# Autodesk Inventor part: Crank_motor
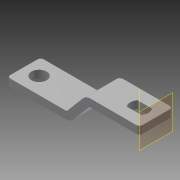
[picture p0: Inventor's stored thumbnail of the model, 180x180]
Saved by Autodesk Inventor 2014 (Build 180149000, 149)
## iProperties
Created: 2006-03
Part Number: Crank_motor
Document SubType Name: Modeling
Designer: debonom
Material: Stainless Steel, 440C
Mass: 73.5464 g
Surface Area: 52.6545 cm^2
Volume: 9.48986 cm^3
Density: 7.75 g/cm^3
Appearance: Steel
Author: debonom
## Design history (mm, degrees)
sketch "Sketch1"
  geometry: L1 (0, 0)-(-34.15, 0); L2 (0, 0)-(12.586, -15); L3 (12.586, -15)-(53.05, -15)
  constraints: 6 end point, 1 horizontal, 1 parallel
  dimensions: "d0" = 130 deg angle of L2 L1; "d1" = 87.2 horizontal distance of L3.end L1.end; "d2" = 34.15 distance of L1.start L1.end; "d3" = 15 distance between parallel lines of L3 L1
workplane "Work Plane1"
sketch "Sketch2"
  geometry: L1 (-11, 2.5)-(11, 2.5); L2 (11, 2.5)-(11, -2.5); L3 (11, -2.5)-(-11, -2.5); L4 (-11, -2.5)-(-11, 2.5); L5 (-11, 2.5)-(11, -2.5); 2 further points
  constraints: 10 end point, 2 parallel, 1 coincident, 1 horizontal, 1 midpoint, 1 perpendicular
  dimensions: "d4" = 22 distance of L1.start L1.end; "d5" = 5 distance of L3.end L1.start
sweep "Sweep1" sketch "Sketch2" dims "d6" = 0
fillet "Fillet1" dims "d7" = 7
fillet "Fillet2" dims "d8" = 2
sketch "Sketch4"
  geometry: L1 (-104.64, 11)-(17.44, 11) reference; L2 (0, 26.4)-(0, -4.4) reference; L3 (-15.823, 7.425)-(-6.178, 7.425); L4 (-6.178, 7.425)-(-6.178, 14.575); L5 (-6.178, 14.575)-(-15.823, 14.575); L6 (-15.823, 14.575)-(-15.823, 7.425); L7 (-15.823, 7.425)-(-6.178, 14.575); A1 r 6 centre (-10.997, 11) between (-6.178, 7.425) and (-6.178, 14.575); A2 r 6 centre (-11.004, 11) between (-15.823, 14.575) and (-15.823, 7.425); 2 further points
  constraints: 10 end point, 4 point on circle, 3 point on line, 2 centre point, 2 parallel, 1 equal radius, 1 horizontal, 1 midpoint, 1 perpendicular
  dimensions: "d18" = 9.645 distance of L3.start L3.end; "d19" = 7.15 distance of L5.end L3.start; "d20" = 6.178 distance from line of L3.end L2; "d21" = 6 radius of A2
extrude "Extrusion3" cut sketch "Sketch4" stored distance "d22" = 10; taper "d23" = 0 deg
sketch "Sketch3"
  geometry: L1 (-17.44, 11)-(104.64, 11) reference; L2 (0, 22)-(0, 0) reference; C1 r 5 at (10, 11); 1 further point
  constraints: 1 centre point, 1 point on line
  dimensions: "d9" = 10 distance from line of C1.centre L2; "d10" = 10 diameter of C1
extrude "Extrusion1" cut sketch "Sketch3" stored distance "d11" = 10; taper "d12" = 0 deg
fillet "Fillet3" dims "d17" = 2
workaxis "Work Axis2"
  workplane "Work Plane3"
body "Solid1"
